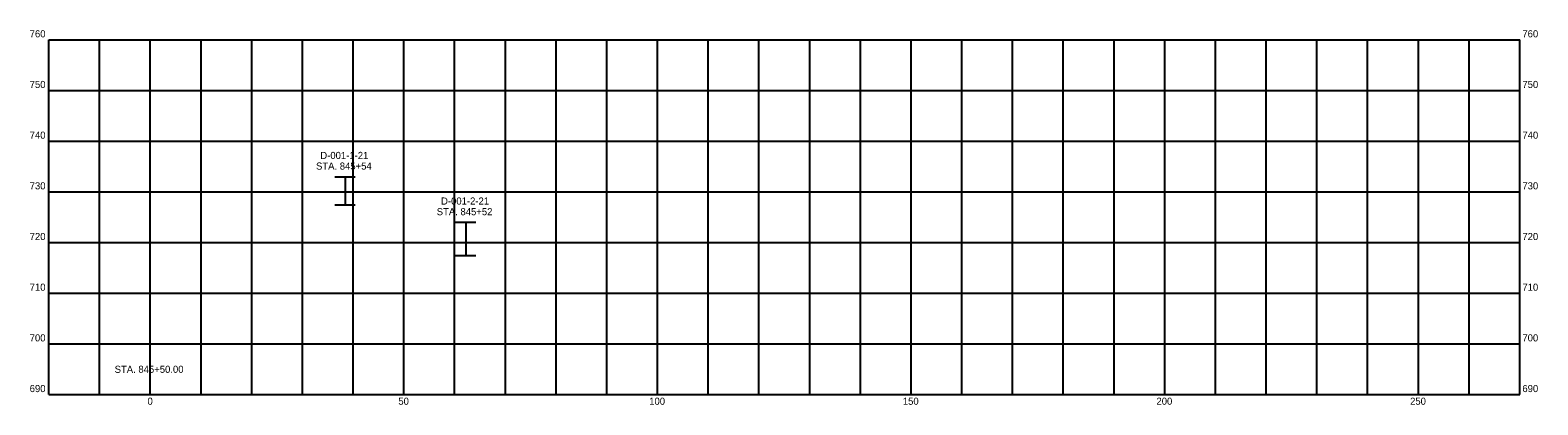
# Model space of a CAD drawing. Extents: x -24 to 274, y 688 to 762.
import ezdxf

# ---------------------------------------------------------------- set-up
doc = ezdxf.new("R2010")
doc.units = 0
for name, color, linetype in [('GT_Project_Soil_Boring', 7, 'Continuous'), ('GT_Project_Text', 7, 'Continuous'), ('GT_Project_Text_3', 7, 'Continuous'), ('SH_Major_Grid_Line', 7, 'Continuous'), ('SH_Text', 7, 'Continuous')]:
    doc.layers.add(name, color=color, linetype=linetype)

msp = doc.modelspace()

# ---------------------------------------------------------------- linework, layer by layer
at = {"layer": 'GT_Project_Soil_Boring'}
for p, q in [((36.4, 733), (40.4, 733)), ((38.4, 733), (38.4, 727.42)), ((36.4, 727.42), (40.4, 727.42)), ((60.2, 724), (64.2, 724)), ((62.2, 724), (62.2, 717.44)), ((60.2, 717.44), (64.2, 717.44))]:
    msp.add_line(p, q, dxfattribs=at)
at = {"layer": 'SH_Major_Grid_Line'}
for p, q in [((-20, 690), (-20, 760)), ((-20, 760), (270, 760)), ((-10, 690), (-10, 760)), ((0, 690), (0, 760)), ((10, 690), (10, 760)), ((20, 690), (20, 760)), ((30, 690), (30, 760)), ((40, 690), (40, 760)), ((50, 690), (50, 760)), ((60, 690), (60, 760)), ((70, 690), (70, 760)), ((80, 690), (80, 760)), ((90, 690), (90, 760)), ((100, 690), (100, 760)), ((110, 690), (110, 760)), ((120, 690), (120, 760)), ((130, 690), (130, 760)), ((140, 690), (140, 760)), ((150, 690), (150, 760)), ((160, 690), (160, 760)), ((170, 690), (170, 760)), ((180, 690), (180, 760)), ((190, 690), (190, 760)), ((200, 690), (200, 760)), ((210, 690), (210, 760)), ((220, 690), (220, 760)), ((230, 690), (230, 760)), ((240, 690), (240, 760)), ((250, 690), (250, 760)), ((260, 690), (260, 760)), ((270, 690), (270, 760)), ((-20, 750), (270, 750)), ((-20, 740), (270, 740)), ((-20, 730), (270, 730)), ((-20, 720), (270, 720)), ((-20, 710), (270, 710)), ((-20, 700), (270, 700)), ((-20, 690), (270, 690))]:
    msp.add_line(p, q, dxfattribs=at)

# ---------------------------------------------------------------- texts
at = {"layer": 'GT_Project_Text'}
for s, p in [('D-001-1-21', (33.52, 736.5)), ('D-001-2-21', (57.32, 727.5))]:
    msp.add_text(s, height=1.4, dxfattribs=at).set_placement(p)
at = {"layer": 'GT_Project_Text_3'}
for s, p in [('STA. 845+54', (32.67, 734.4)), ('STA. 845+52', (56.47, 725.4))]:
    msp.add_text(s, height=1.4, dxfattribs=at).set_placement(p)
at = {"layer": 'SH_Text'}
for s, p in [('760', (-23.78, 760.5)), ('760', (270.5, 760.5)), ('750', (-23.78, 750.5)), ('750', (270.5, 750.5)), ('740', (-23.78, 740.5)), ('740', (270.5, 740.5)), ('730', (-23.78, 730.5)), ('730', (270.5, 730.5)), ('720', (-23.78, 720.5)), ('720', (270.5, 720.5)), ('710', (-23.78, 710.5)), ('710', (270.5, 710.5)), ('700', (-23.78, 700.5)), ('700', (270.5, 700.5)), ('STA. 845+50.00', (-7.03, 694.3)), ('690', (-23.78, 690.5)), ('690', (270.5, 690.5)), ('0', (-0.55, 688)), ('50', (48.9, 688)), ('100', (98.36, 688)), ('150', (148.36, 688)), ('200', (198.36, 688)), ('250', (248.36, 688))]:
    msp.add_text(s, height=1.4, dxfattribs=at).set_placement(p)

doc.saveas('drawing.dxf')
